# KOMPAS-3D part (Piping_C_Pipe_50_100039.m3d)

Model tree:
1. Plane XY
2. Plane ZX
3. Plane ZY
4. X Axis
5. Y Axis
6. Z Axis
7. Origin
8. Path  (labels: Труба Dy 50; Переход Dy 50-150)
9. Plane of section
10. Section of pipe
11. Pipe
     Толщина стенки 1 = 1

Referenced files in C:\Program Files\ASCON\KOMPAS-3D V10\Libs\Piping\Models\Tanks\: Tanks.a3d
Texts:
  Pipe Dn 50
  Steel ASTM A295
  Three Point Plane
  Plane at Angle
  Line and Point Plane
  Axis through Two Vertices
  Axis of Feature
  Axis of Conical Surface
  Axis through Edge
  Приклеить элемент выдавливания
  Приклеить элемент вращения
  Приклеить кинематический элемент
  Приклеить элемент по сечениям
  Trim by Surface
  Trim by Sketch
  Feature with No History
  Intersection Axis of Two Planes
  Two Line Plane
  Line and Face Plane
  Bend by line
  Hole in sheet body
  Cut in sheet body
  Point in CM
  Linear Dimension from Line to Point
  Surface Finish Symbol
  Geometric Tolerance Symbol
  Текст на чертеже
  Линия-выноска #1
  Линия-выноска #2
  Линия-выноска #3
  Отклонения формы и база
  Марка координационной оси
  Марка/позиционное обозначение с линией-выноской
  Марка/позиционное обозначение на линии
  Марка/позиционное обозначение без линии-выноски
  Труба Dy 50
  Переход Dy 50-150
